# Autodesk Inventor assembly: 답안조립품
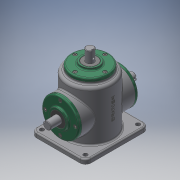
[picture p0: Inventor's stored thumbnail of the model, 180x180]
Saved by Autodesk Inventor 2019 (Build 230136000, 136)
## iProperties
Created: 2020-12
Part Number: 답안조립품
Material: 일반
Document SubType Name: Assembly
Designer: jun-1-11
Author: jun-1-11
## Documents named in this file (16)
- C:\Users\jun-1-11\Desktop\701207V1007\답안조립품.iam
- C:\Users\jun-1-11\Desktop\701207V1007\본체.ipt
- C:\Users\jun-1-11\Desktop\701207V1007\메인 베벨기어.ipt
- C:\Users\jun-1-11\Desktop\701207V1007\메인 축.ipt
- 메인 축.ipt
- C:\Users\jun-1-11\Desktop\701207V1007\베어링 6203.ipt
- C:\Users\jun-1-11\Desktop\701207V1007\볼트 M4.ipt
- 볼트 M4.ipt
- C:\Users\jun-1-11\Desktop\701207V1007\서브 베벨기어.ipt
- C:\Users\jun-1-11\Desktop\701207V1007\서브 축.ipt
- 서브 축.ipt
- C:\Users\jun-1-11\Desktop\701207V1007\오일 실.ipt
- 오일 실.ipt
- C:\Users\jun-1-11\Desktop\701207V1007\커버.ipt
- C:\Users\jun-1-11\Desktop\701207V1007\키 4x4.ipt
- C:\Users\jun-1-11\Desktop\701207V1007\키 5x5.ipt
